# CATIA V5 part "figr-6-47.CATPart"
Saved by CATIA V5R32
Part number: Part1
Bounding box of the stored display mesh (mm): x 0 to 100, y -60 to 60, z -50 to 50
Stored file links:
  D:\PROJECTS\Project 2022\CATIA V5 6R 2022\Resources\Part Files\c06_catia_v5_6r2022_prt\figr-6-47.CATPart
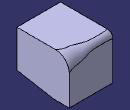
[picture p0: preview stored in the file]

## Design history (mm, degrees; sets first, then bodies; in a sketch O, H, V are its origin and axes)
Body1 (main body)
  Sketch1 on yz-plane, origin (0, 0, 0), H (0, 1, 0), V (0, 0, 1)
    line L1 (60, 50) -> (60, -50)
    line L2 (60, -50) -> (25, -50)
    line L3 (-60, -35) -> (-60, 50)
    line L4 (-60, 50) -> (60, 50)
    point P2 (60, -50)
    point P3 (-60, -50)
    line L5 (25, -50) -> (-60, -35)
    point P5 (25, -50)
    point P6 (-60, -35)
    length L1 = 100
    distance P2 P3 = 120
    distance P5 P3 = 85
    distance P6 P3 = 15
    vertical: L1 V, L3 V
    horizontal: L2 H, L4 H
    equidistance: L1 L3 O, L2 L4 O
    coincidence: L2 P3, L3 P3
  Pad1: profile Sketch1, direction (1, 0, 0), length 100
  Sketch2 on face of Pad1 from Sketch1.L1, origin (0, 60, 0), H (-1, 0, 0), V (0, 0, 1)
    spline S1 through (-100, 18.28) (-85.0256, 26.4663) (-71, 29) (-63.0256, 32.4663) (-31, 39) (-16, 39) (0, 37.4663)
    reference projected line E1 (-100, -50) -> (-100, 50) from edge [face of Pad1 from Sketch1.L1 | end face of Pad1]
    reference projected line E2 (0, -50) -> (0, 50) from edge [start face of Pad1 | face of Pad1 from Sketch1.L1]
    point P1 (0, 37.4663)
    point P2 (-100, 18.28)
    coincidence: P1 V, P2 E1, P1 E2
  Sketch3 on face of Pad1 from Sketch1.L4, origin (0, 0, 50), H (1, 0, 0), V (0, 1, 0)
    projected line E1 (0, 60) -> (100, 60) from Sketch2.S1
  FaceFillet1: ConicRatio 0.5, Face1 face of Pad1 from Sketch1.L1, Face2 face of Pad1 from Sketch1.L4, HoldCurve Sketch2, Radius 5, Spine Sketch3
